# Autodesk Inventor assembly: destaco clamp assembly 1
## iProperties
Author: Rich
Shininess: 20.0
PropertySet Name: _Private Model Information
Created: 2001-04
Part Number: destaco clamp assembly 1
Document SubType Name: Assembly
Designer: Rich
Control State: 0
Master: False
Checked Out: False
PropertySet Name: Design Tracking Control
Density: 0.0
Volumn: 0.0
Area: 0.0
PropertySet Name: Model Information
